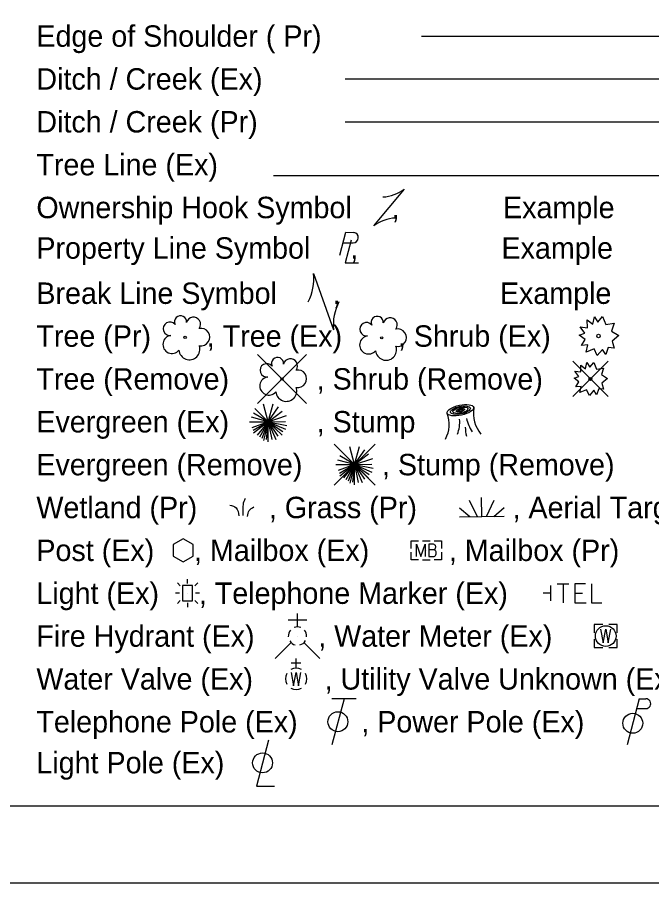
# Model space of a CAD drawing. Extents: x 0 to 43.4, y -8.1 to 22.
# Drawn here: x 8.05 to 12.2, y 0 to 5.65 of the extents above; entities that cross this region are included whole.
import ezdxf

# ---------------------------------------------------------------- set-up
doc = ezdxf.new("R2010")
doc.units = 0
for name, color, linetype in [('SH_Border', 7, 'Continuous'), ('SH_Cut_Line', 7, 'Continuous'), ('SH_Text', 7, 'Continuous')]:
    doc.layers.add(name, color=color, linetype=linetype)

msp = doc.modelspace()

# ---------------------------------------------------------------- linework, layer by layer
at = {"layer": 'SH_Border'}
msp.add_lwpolyline([(1.5, 21.5), (33.5, 21.5), (33.5, 0.5), (1.5, 0.5)], close=True, dxfattribs=at)
at = {"layer": 'SH_Cut_Line'}
msp.add_lwpolyline([(0, 0), (34, 0), (34, 22), (0, 22)], close=True, dxfattribs=at)
at = {"layer": 'SH_Text'}
for p, q in [((10.6951, 5.5316), (14.1785, 5.5316)), ((10.1947, 5.2516), (14.0947, 5.2516)), ((10.1947, 4.9716), (14.0947, 4.9716)), ((9.7271, 4.6216), (14.0771, 4.6216)), ((10.3821, 4.2916), (10.5821, 4.5316)), ((10.4821, 4.4116), (10.4821, 4.4116)), ((10.1823, 4.1806), (10.2472, 4.1806)), ((10.2224, 4.1494), (10.2224, 4.1494)), ((9.9896, 3.9802), (10.1196, 3.6119)), ((10.0546, 3.796), (10.0546, 3.796)), ((9.6225, 3.4519), (9.9432, 3.1312)), ((9.9432, 3.4519), (9.6225, 3.1312)), ((11.6816, 3.4075), (11.9133, 3.1757)), ((11.9133, 3.4075), (11.6816, 3.1757)), ((9.7828, 3.2916), (9.7828, 3.2916)), ((11.7974, 3.2916), (11.7974, 3.2916)), ((9.6933, 3.0114), (9.6625, 3.1267)), ((9.6933, 3.0114), (9.7247, 3.1288)), ((9.6933, 3.0114), (9.5957, 3.0688)), ((9.6933, 3.0114), (9.6061, 3.0985)), ((9.6933, 3.0114), (9.7597, 3.1085)), ((9.6933, 3.0114), (9.7847, 3.0815)), ((9.57, 3.0114), (9.6933, 3.0114)), ((9.6933, 3.0114), (9.583, 3.041)), ((9.6933, 3.0114), (9.5861, 2.9723)), ((9.6933, 3.0114), (9.5937, 2.9543)), ((9.6933, 3.0114), (9.5957, 2.9365)), ((9.6933, 3.0114), (9.6197, 2.9247)), ((9.6933, 3.0114), (9.6354, 2.911)), ((9.6933, 3.0114), (9.6517, 2.9029)), ((9.6933, 3.0114), (9.6617, 2.89)), ((9.6933, 3.0114), (9.6798, 2.8966)), ((9.6933, 3.0114), (9.8117, 3.0515)), ((9.6933, 3.0114), (9.8061, 3.0137)), ((9.6933, 2.8804), (9.6933, 3.0114)), ((9.6933, 3.0114), (9.7164, 2.8955)), ((9.6933, 3.0114), (9.7417, 2.8947)), ((9.6933, 3.0114), (9.7567, 2.9165)), ((9.6933, 3.0114), (9.783, 2.9233)), ((9.6933, 3.0114), (9.7889, 2.9475)), ((9.6933, 3.0114), (9.805, 2.9628)), ((9.6933, 3.0114), (9.814, 2.9874)), ((10.967, 3.0116), (10.967, 3.0116)), ((10.1237, 2.8652), (10.391, 2.5979)), ((10.391, 2.8652), (10.1237, 2.5979)), ((10.2573, 2.7316), (10.2265, 2.8469)), ((10.2573, 2.7316), (10.2888, 2.8491)), ((10.2573, 2.7316), (10.3237, 2.8287)), ((10.2573, 2.7316), (10.1597, 2.789)), ((10.2573, 2.7316), (10.1701, 2.8188)), ((10.2573, 2.7316), (10.3488, 2.8017)), ((10.2573, 2.7316), (10.3758, 2.7718)), ((10.134, 2.7316), (10.2573, 2.7316)), ((10.2573, 2.7316), (10.147, 2.7612)), ((10.2573, 2.7316), (10.1501, 2.6926)), ((10.2573, 2.7316), (10.1578, 2.6746)), ((10.2573, 2.7316), (10.1597, 2.6567)), ((10.2573, 2.7316), (10.1837, 2.6449)), ((10.2573, 2.7316), (10.1994, 2.6312)), ((10.2573, 2.7316), (10.2157, 2.6231)), ((10.2573, 2.7316), (10.2258, 2.6102)), ((10.2573, 2.7316), (10.2438, 2.6168)), ((10.2573, 2.7316), (10.3701, 2.7339)), ((10.2573, 2.6006), (10.2573, 2.7316)), ((10.2573, 2.7316), (10.2804, 2.6157)), ((10.2573, 2.7316), (10.3057, 2.6149)), ((10.2573, 2.7316), (10.3208, 2.6368)), ((10.2573, 2.7316), (10.347, 2.6436)), ((10.2573, 2.7316), (10.3529, 2.6677)), ((10.2573, 2.7316), (10.369, 2.6831)), ((10.2573, 2.7316), (10.378, 2.7076)), ((10.2573, 2.7316), (10.2573, 2.7316)), ((11.059, 2.3912), (11.0068, 2.4972)), ((11.0889, 2.3916), (11.0871, 2.5171)), ((11.1189, 2.3921), (11.1679, 2.4996)), ((11.0103, 2.3904), (10.942, 2.4475)), ((11.1677, 2.3928), (11.2342, 2.4519)), ((10.9428, 2.3894), (11.235, 2.3938)), ((10.7001, 2.2327), (10.7502, 2.2327)), ((10.7257, 2.1716), (10.7257, 2.1716)), ((10.7001, 2.1105), (10.7502, 2.1105)), ((9.166, 1.9556), (9.166, 1.9822)), ((9.1178, 1.94), (9.0993, 1.9588)), ((9.2327, 1.9588), (9.2141, 1.94)), ((11.5387, 1.8416), (11.5387, 1.9416)), ((9.1139, 1.8919), (9.0873, 1.8919)), ((9.166, 1.8916), (9.166, 1.8916)), ((9.2448, 1.8919), (9.2181, 1.8919)), ((11.5387, 1.8916), (11.4889, 1.8916)), ((9.1178, 1.8432), (9.0993, 1.8244)), ((9.166, 1.8276), (9.166, 1.801)), ((9.2327, 1.8244), (9.2141, 1.8432)), ((9.8841, 1.6718), (9.8841, 1.7578)), ((9.9441, 1.7148), (9.8241, 1.7148)), ((9.8841, 1.6116), (9.8841, 1.6116)), ((9.8841, 1.6116), (9.8841, 1.6116)), ((11.8977, 1.6116), (11.8977, 1.6116)), ((9.8418, 1.5692), (9.7378, 1.4653)), ((9.9264, 1.5692), (10.0304, 1.4653)), ((9.9067, 1.4334), (9.8432, 1.4334)), ((9.875, 1.4016), (9.875, 1.4652)), ((9.875, 1.3316), (9.875, 1.3316)), ((10.188, 1.2016), (10.1077, 0.9016)), ((10.268, 1.2016), (10.108, 1.2016)), ((12.117, 1.2016), (12.0367, 0.9016)), ((12.117, 1.2016), (12.1595, 1.2016)), ((12.0999, 1.1378), (12.1595, 1.1378))]:
    msp.add_line(p, q, dxfattribs=at)
for points in [[(10.1613, 4.101), (10.2004, 4.2493), (10.2521, 4.2492)], [(10.2358, 4.1974), (10.1962, 4.0496), (10.2835, 4.0496)], [(11.8462, 3.6621), (11.8764, 3.6988), (11.8972, 3.6462), (11.9518, 3.6552), (11.9348, 3.6046), (11.9821, 3.5748), (11.9393, 3.5381), (11.9518, 3.4924), (11.9141, 3.4958), (11.8978, 3.4502), (11.8764, 3.4848), (11.8425, 3.4439), (11.8211, 3.4883), (11.7701, 3.4668), (11.7797, 3.5138), (11.7391, 3.5097), (11.7628, 3.5492), (11.7243, 3.5776), (11.7613, 3.5908), (11.7309, 3.6309), (11.7775, 3.6254), (11.776, 3.6773), (11.8137, 3.6489), (11.824, 3.6982), (11.8462, 3.6621)], [(11.7938, 3.3685), (11.8196, 3.3998), (11.8372, 3.355), (11.8836, 3.3626), (11.8692, 3.3196), (11.9094, 3.2944), (11.873, 3.2631), (11.8836, 3.2243), (11.8516, 3.2272), (11.8378, 3.1884), (11.8196, 3.2178), (11.7907, 3.1831), (11.7725, 3.2208), (11.7292, 3.2025), (11.7373, 3.2425), (11.7028, 3.239), (11.7229, 3.2725), (11.6903, 3.2967), (11.7217, 3.3079), (11.6959, 3.342), (11.7355, 3.3374), (11.7342, 3.3815), (11.7662, 3.3573), (11.775, 3.3992), (11.7938, 3.3685)], [(9.0728, 2.1341), (9.1377, 2.0966), (9.2027, 2.1341), (9.2027, 2.2091), (9.1377, 2.2466), (9.0728, 2.2091), (9.0728, 2.1341)], [(10.6257, 2.1842), (10.6257, 2.2327), (10.6742, 2.2327)], [(10.6609, 2.1316), (10.6609, 2.2116), (10.6898, 2.1316), (10.7176, 2.2116), (10.7176, 2.1316)], [(10.7768, 2.1751), (10.7799, 2.1782), (10.7818, 2.1801), (10.7831, 2.182), (10.7837, 2.1832), (10.785, 2.1858), (10.7856, 2.1877), (10.7869, 2.1921), (10.7869, 2.194), (10.7869, 2.1965), (10.7862, 2.2003), (10.785, 2.2034), (10.7831, 2.2059), (10.7799, 2.2084), (10.7774, 2.2097), (10.7761, 2.2103), (10.773, 2.2116), (10.7421, 2.2116), (10.7421, 2.1316), (10.7768, 2.1316), (10.7812, 2.1341), (10.785, 2.1373), (10.7881, 2.1423), (10.79, 2.148), (10.7906, 2.1536), (10.7906, 2.1574), (10.7894, 2.1612), (10.7869, 2.1669), (10.7837, 2.1707), (10.7768, 2.1751), (10.7421, 2.1751)], [(10.776, 2.2327), (10.8257, 2.2327), (10.8257, 2.1842)], [(10.6742, 2.1105), (10.6257, 2.1105), (10.6257, 2.159)], [(10.8257, 2.159), (10.8257, 2.1105), (10.776, 2.1105)], [(11.5795, 1.9537), (11.6573, 1.9537)], [(11.6189, 1.9537), (11.6189, 1.8287)], [(11.7645, 1.9537), (11.6966, 1.9537), (11.6966, 1.8287), (11.7694, 1.8287)], [(11.8039, 1.9537), (11.8039, 1.8287), (11.8718, 1.8287)], [(11.6966, 1.8917), (11.7448, 1.8917)], [(11.8777, 1.6866), (11.8227, 1.6866), (11.8227, 1.6316)], [(11.8644, 1.6566), (11.881, 1.5666), (11.8977, 1.6566), (11.9144, 1.5666), (11.931, 1.6566)], [(11.9727, 1.6316), (11.9727, 1.6866), (11.9177, 1.6866)], [(11.8227, 1.5916), (11.8227, 1.5366), (11.8777, 1.5366)], [(11.9177, 1.5366), (11.9727, 1.5366), (11.9727, 1.5916)], [(9.8432, 1.3726), (9.8591, 1.2864), (9.875, 1.3726), (9.891, 1.2864), (9.9068, 1.3726)], [(9.6953, 0.9303), (9.6165, 0.6311), (9.7347, 0.6311)]]:
    msp.add_lwpolyline(points, dxfattribs=at)
msp.add_lwpolyline([(9.1327, 1.8416), (9.1993, 1.8416), (9.1993, 1.9416), (9.1327, 1.9416)], close=True, dxfattribs=at)
for centre, radius in [((9.1498, 3.5635), 0.0084), ((10.4344, 3.56), 0.0072), ((11.8504, 3.5716), 0.0115), ((9.7828, 3.2916), 0.0072), ((11.7974, 3.2916), 0.00979), ((11.8977, 1.6116), 0.0675), ((10.1479, 1.0516), 0.065), ((12.0742, 1.0416), 0.065), ((9.6559, 0.7827), 0.065)]:
    msp.add_circle(centre, radius, dxfattribs=at)
for centre, radius, start, end in [((10.4239, 4.7465), 0.2668, 273.6945, 306.337), ((10.5402, 4.0766), 0.2668, 93.6945, 126.337), ((10.2469, 4.2151), 0.0345, 270.471, 81.3281), ((9.6577, 3.9477), 0.3335, 332.9422, 5.5848), ((10.4516, 3.6444), 0.3335, 152.9422, 185.5848), ((9.1203, 3.6645), 0.0395, 354.0047, 205.9741), ((9.2046, 3.6484), 0.0466, 323.83, 165.0376), ((10.4049, 3.6611), 0.0395, 354.0047, 205.9741), ((10.4892, 3.6449), 0.0466, 323.83, 165.0376), ((9.0505, 3.6194), 0.0441, 39.0625, 279.5412), ((9.2536, 3.5646), 0.0574, 259.1453, 101.4596), ((10.3351, 3.616), 0.0441, 39.0625, 279.5412), ((9.0642, 3.517), 0.0592, 96.1722, 320.5737), ((10.3488, 3.5136), 0.0592, 96.1722, 320.5737), ((10.5382, 3.5611), 0.0574, 259.1453, 101.4596), ((9.1782, 3.4853), 0.0685, 184.9476, 19.4572), ((10.4628, 3.4819), 0.0685, 184.9476, 19.4572), ((9.7533, 3.3926), 0.0395, 354.0047, 205.9741), ((9.8376, 3.3764), 0.0466, 323.83, 165.0376), ((9.6835, 3.3475), 0.0441, 39.0625, 279.5412), ((9.8866, 3.2926), 0.0574, 259.1453, 101.4596), ((9.6972, 3.2451), 0.0592, 96.1722, 320.5737), ((9.8112, 3.2134), 0.0685, 184.9476, 19.4572), ((10.6754, 2.9943), 0.2001, 331.5338, 20.9269), ((11.2472, 3.0686), 0.2146, 171.4106, 219.9194), ((10.6911, 3.0129), 0.2527, 340.7938, 3.5481), ((11.2924, 3.1144), 0.316, 194.9653, 212.1216), ((11.1622, 2.9716), 0.1819, 178.7926, 197.1224), ((9.8841, 1.6116), 0.06, 140.021, 184.0629), ((9.8841, 1.6116), 0.06, 68.1395, 112.038), ((9.8841, 1.6116), 0.06, 356.0165, 39.9889), ((9.8841, 1.6116), 0.06, 211.8788, 255.8479), ((9.8841, 1.6116), 0.06, 283.8239, 329.9097), ((9.875, 1.3317), 0.07, 150.0184, 209.9816), ((9.875, 1.3317), 0.07, 60.0184, 120.0157), ((9.875, 1.3317), 0.07, 330.0184, 29.9816), ((9.875, 1.3317), 0.07, 239.9843, 299.9816), ((12.1601, 1.1697), 0.0319, 268.8767, 91.1233)]:
    msp.add_arc(centre, radius, start, end, dxfattribs=at)
for major_axis in [(0.0868, 0.0187), (0.0651, 0.0141), (0.0488, 0.0105), (0.0275, 0.0059), (0.0154, 0.0033)]:
    msp.add_ellipse((10.9482, 3.0871), major_axis=major_axis, ratio=0.36865, dxfattribs=at)
for points in [[(9.5294, 2.4002), (9.5294, 2.4475), (9.5353, 2.4919), (9.5441, 2.5127)], [(9.4421, 2.4672), (9.4835, 2.4495), (9.5012, 2.3962)], [(9.5571, 2.393), (9.569, 2.4314), (9.5985, 2.4552)]]:
    msp.add_spline(points, degree=3, dxfattribs=at)

# ---------------------------------------------------------------- texts
for s, p in [('Edge of Shoulder ( Pr)', (8.1785, 5.4616)), ('Ditch / Creek (Ex)', (8.1785, 5.1816)), ('Ditch / Creek (Pr)', (8.1785, 4.9016)), ('Tree Line (Ex)', (8.1785, 4.6216)), ('Ownership Hook Symbol     ,             Example', (8.1785, 4.3416)), ('Property Line Symbol     ,                  Example', (8.1785, 4.077)), ('Break Line Symbol       ,                    Example', (8.1785, 3.7816)), ('Tree (Pr)       , Tree (Ex)       , Shrub (Ex)', (8.1785, 3.5016)), ('Tree (Remove)           , Shrub (Remove)', (8.1785, 3.2216)), ('Evergreen (Ex)           , Stump ', (8.1785, 2.9416)), ('Evergreen (Remove)          , Stump (Remove)', (8.1785, 2.6616)), ('Wetland (Pr)         , Grass (Pr)            , Aerial Target    ', (8.1785, 2.3816)), ('Post (Ex)     , Mailbox (Ex)          , Mailbox (Pr)', (8.1785, 2.1016)), ('Light (Ex)     , Telephone Marker (Ex)     ', (8.1785, 1.8216)), ('Fire Hydrant (Ex)        , Water Meter (Ex)', (8.1785, 1.5416)), ('Water Valve (Ex)         , Utility Valve Unknown (Ex.)', (8.1785, 1.2616)), ('Telephone Pole (Ex)        , Power Pole (Ex)', (8.1785, 0.9816)), ('Light Pole (Ex)     ', (8.1785, 0.7145))]:
    msp.add_text(s, height=0.14, dxfattribs=at).set_placement(p)

doc.saveas('drawing.dxf')
